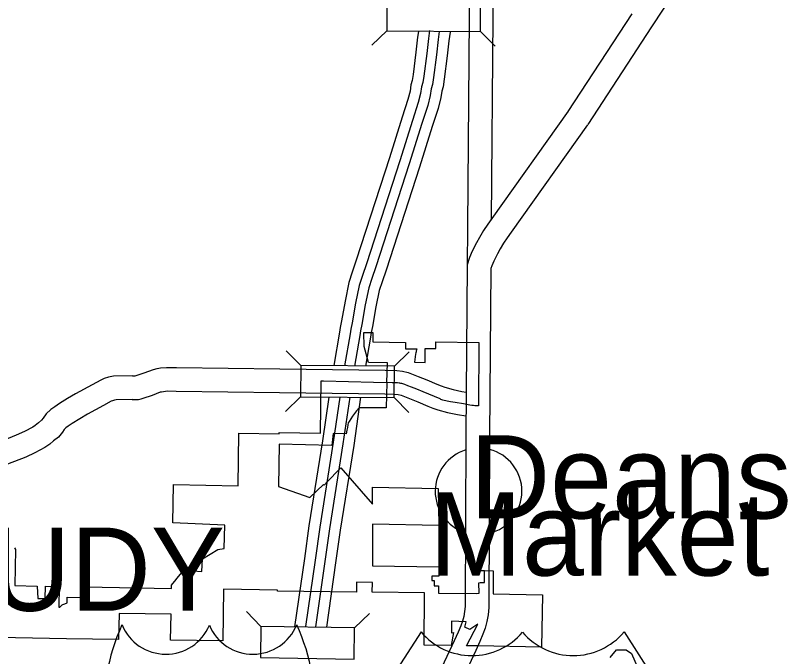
# Model space of a CAD drawing. Extents: x 535214 to 694517, y 381272 to 484355.
# Drawn here: x 552787 to 557684, y 468091 to 472159 of the extents above; entities that cross this region are included whole.
import ezdxf

# ---------------------------------------------------------------- set-up
doc = ezdxf.new("R2010")
doc.units = 0
for name, color, linetype in [('Level 11', 7, 'Continuous'), ('Level 15', 7, 'Continuous'), ('Level 19', 7, 'Continuous'), ('Level 20', 7, 'Continuous'), ('Level 22', 7, 'Continuous'), ('Level 23', 7, 'Continuous'), ('Level 24', 7, 'Continuous'), ('Level 6', 7, 'Continuous')]:
    doc.layers.add(name, color=color, linetype=linetype)

msp = doc.modelspace()

# ---------------------------------------------------------------- linework, layer by layer
at = {"layer": 'Level 11'}
for points in [[(555671.9, 472817.1), (555664.7, 472146.8), (555653.8, 470819.8), (555651.7, 470565.2)], [(555821.9, 472815.5), (555814.7, 472145.4), (555804.1, 470860.1)], [(553529.4, 469871.8), (553545.8, 469871.7), (553552, 469873.5), (553604.4, 469890.9), (553661.7, 469913.1), (553684.9, 469918.6), (553706.7, 469922), (553745.2, 469925.9), (553807.4, 469925.4), (554463.7, 469916.9), (555132.2, 469908.5), (555205, 469905.9), (555240.9, 469900.7), (555276.8, 469893.1), (555340.4, 469867.4), (555395.5, 469846.2), (555459.7, 469819), (555486.1, 469808.3), (555509.7, 469800.4), (555562.8, 469785.5), (555617.7, 469773.5), (555646.4, 469768.9)], [(553527.4, 469871.8), (553408.4, 469869.8), (553377.3, 469862.9), (553349.9, 469854.6), (553329.1, 469845.4), (553273.6, 469815.4), (553168.6, 469758.1), (553117.8, 469727.1), (553066.9, 469695.8), (553036.4, 469676.2), (553011.2, 469657.5), (552981.4, 469630.8), (552963.7, 469603.5), (552953.1, 469590.3), (552932.7, 469574), (552912.8, 469556.4), (552897.3, 469545.9), (552844.8, 469519.1), (552792.3, 469494.6), (552677.1, 469448.4)], [(553528, 469721.8), (553568, 469721.5), (553584.7, 469726.8), (553596.1, 469730.1), (553655.2, 469749.7), (553706.2, 469769.5), (553713.8, 469771.3), (553725.9, 469773.2), (553752.2, 469775.8), (553805.8, 469775.4), (554461.8, 469766.9), (555128.6, 469758.5), (555191.6, 469756.3), (555214.6, 469753), (555232.7, 469749.1), (555285.3, 469727.9), (555339.3, 469707.1), (555402.4, 469680.4), (555434.1, 469667.6), (555465.6, 469657), (555526.5, 469639.9), (555589.7, 469626.1), (555643, 469617.5)], [(553530, 469721.9), (553426.2, 469720.1), (553415.5, 469717.7), (553402.1, 469713.6), (553395.1, 469710.6), (553345.2, 469683.6), (553243.6, 469628.1), (553196.2, 469599.2), (553146.7, 469568.7), (553121.7, 469552.8), (553106.2, 469541.2), (553096.4, 469532.4), (553085.5, 469515.5), (553059.6, 469483.4), (553029.3, 469459.2), (553004.7, 469437.5), (552973.6, 469416.5), (552910.8, 469384.3), (552852, 469356.9), (552737.4, 469311)]]:
    msp.add_lwpolyline(points, dxfattribs=at)
at = {"layer": 'Level 15'}
for points in [[(557034.5, 472411.9), (556821.5, 472086.8), (556416.2, 471467)], [(556696, 472168.9), (556290.7, 471549.1)], [(556292.3, 471551.5), (555807.6, 470869.6), (555783.4, 470834.7), (555755, 470794.5), (555729.6, 470750.7), (555711, 470715.8), (555684.1, 470663.2), (555667.1, 470623.7), (555651.8, 470576.8), (555643.9, 469490.7), (555638.7, 468408.7), (555635.7, 468376.9), (555629.6, 468344.6), (555622, 468314.9), (555611.8, 468286.5), (555594.6, 468246.1), (555570.3, 468190.1), (555335.5, 467689.3)], [(556414.6, 471464.6), (555930.3, 470783.3), (555906.3, 470748.7), (555881.4, 470713.5), (555860.7, 470677.8), (555844, 470646.4), (555820, 470599.4), (555807.6, 470570.7), (555801.6, 470552.4), (555793.9, 469489.8), (555788.6, 468401.3), (555784.4, 468356), (555776.2, 468312.1), (555765.5, 468270.6), (555751.5, 468231.8), (555732.5, 468186.9), (555707, 468128.4), (555471.3, 467625.7)]]:
    msp.add_lwpolyline(points, dxfattribs=at)
at = {"layer": 'Level 19'}
for points in [[(555342.3, 472056.5), (555337.8, 472021.8), (555327, 471925.5), (555308.8, 471783.9), (555302.6, 471746.9), (555295.5, 471718.4), (555289.3, 471678.2), (555275.6, 471625), (555239.3, 471514.1), (555158.7, 471256.2), (554947.9, 470605.4), (554921.9, 470530.6), (554900.6, 470463.3), (554877, 470346.7), (554854, 470221.1), (554845.9, 470178.9), (554841.6, 470148.4), (554805.5, 469937.3)], [(555412.6, 472063.6), (555406, 472013.5), (555395.3, 471917.3), (555376.8, 471773.8), (555369.9, 471732.8), (555362.9, 471704.9), (555356.7, 471664.3), (555341.6, 471605.7), (555304.8, 471493.1), (555224.2, 471235.3), (555013.1, 470583.6), (554987.2, 470508.9), (554967.2, 470446), (554944.5, 470333.7), (554921.6, 470208.5), (554913.7, 470167.6), (554909.5, 470137.8), (554874.8, 469934.5)], [(555474.7, 472056.4), (555468.1, 472006), (555457.3, 471909.8), (555438.7, 471764.6), (555431.1, 471720.1), (555424.3, 471692.6), (555418.1, 471651.7), (555401.6, 471588.1), (555364.3, 471474.1), (555283.8, 471216.4), (555072.3, 470563.7), (555046.5, 470489.2), (555027.8, 470430.3), (555005.9, 470321.9), (554983, 470196.9), (554975.4, 470157.4), (554971.3, 470128.2), (554938.1, 469933.9)], [(555543.6, 472053.2), (555536.3, 471997.6), (555525.6, 471901.6), (555506.7, 471754.4), (555498.5, 471706), (555491.8, 471679.1), (555485.5, 471637.9), (555467.6, 471568.8), (555429.8, 471453.1), (555349.3, 471195.5), (555137.5, 470541.8), (555111.8, 470467.5), (555094.5, 470413.1), (555073.4, 470308.9), (555050.6, 470184.3), (555043.2, 470146.1), (555039.2, 470117.6), (555007.8, 469933.7)], [(554774.5, 469737.6), (554734.3, 469460.5), (554648.4, 468921.1), (554619.6, 468712.3), (554557.3, 468279.7)], [(554843.8, 469737), (554802.3, 469450.1), (554716.4, 468911), (554687.7, 468702.7), (554626.9, 468280.6)], [(554906.9, 469736.5), (554864.1, 469440.7), (554778.2, 468901.9), (554749.6, 468694), (554689.9, 468279.6)], [(554976.3, 469736), (554932.1, 469430.4), (554846.2, 468891.8), (554817.7, 468684.4), (554759.1, 468277.7)]]:
    msp.add_lwpolyline(points, dxfattribs=at)
at = {"layer": 'Level 20'}
for p, q in [((555141.8, 472062), (555047.7, 471969.4)), ((555735.7, 472057.3), (555828.3, 471963.2)), ((554596, 469937), (554503.4, 470031.1)), ((555190, 469932.3), (555284.1, 470024.9)), ((554594.5, 469739), (554500.4, 469646.4)), ((555188.4, 469734.3), (555281, 469640.2)), ((554344.2, 468282.4), (554252.4, 468377.3)), ((554938.1, 468272.4), (555033, 468364.2))]:
    msp.add_line(p, q, dxfattribs=at)
for points in [[(555141.8, 472062), (555735.7, 472057.3), (555737.3, 472255.3), (555143.3, 472260)], [(554594.5, 469739), (555188.4, 469734.3), (555190, 469932.3), (554596, 469937)], [(554938.1, 468272.4), (554344.2, 468282.4), (554340.8, 468084.4), (554934.7, 468074.5)]]:
    msp.add_lwpolyline(points, close=True, dxfattribs=at)
at = {"layer": 'Level 22'}
for p, q in [((555359.5, 468246.8), (555186.4, 467979.1)), ((556646.4, 468246.8), (556819.5, 467979.1))]:
    msp.add_line(p, q, dxfattribs=at)
for centre, start, end in [((555681.8, 468518), 220.075, 319.6701), ((556324.1, 468518), 220.3299, 319.925)]:
    msp.add_arc(centre, 421.2, start, end, dxfattribs=at)
at = {"layer": 'Level 23'}
for centre, radius, start, end in [((554579.6, 467776.6), 1230.1, 155.2204, 185.7928), ((553740.4, 468405.2), 299.7, 202.1459, 337.3414), ((554293.4, 468405.2), 299.7, 202.6586, 337.8541), ((553454.1, 467776.6), 1230.1, 354.2072, 24.7796)]:
    msp.add_arc(centre, radius, start, end, dxfattribs=at)
at = {"layer": 'Level 24'}
for start, end in [(107.1701, 251.8503), (284.3535, 75.3582)]:
    msp.add_arc((555724.1, 469139), 275, start, end, dxfattribs=at)
at = {"layer": 'Level 6'}
for points in [[(555026, 469956), (554997.5, 470058.7), (554995.8, 470147.1), (555053.8, 470146.1), (555053, 470087.5), (555261.5, 470084), (555261.2, 470043.5), (555332.4, 470042.3), (555330.6, 470035.8), (555328.9, 470029.6), (555327.4, 470023.7), (555326.4, 470018.6), (555325, 470009.1), (555322.5, 469993.6), (555317.3, 469958.8), (555385.6, 469957.6), (555386.3, 470045.6), (555452.2, 470044.5), (555452.6, 470088.3), (555726.3, 470083.7), (555723.5, 469681), (555700.4, 469682.5), (555691, 469683.4), (555682, 469684.6), (555669.6, 469686.5), (555659.1, 469688.3), (555627.8, 469693.7), (555576.6, 469702), (555546.7, 469706.9), (555535.4, 469709), (555525.9, 469710.8), (555517.5, 469712.7), (555506.4, 469715.7), (555497.9, 469718.4), (555485.3, 469722.8), (555479.5, 469725), (555445.5, 469739.8), (555373.5, 469771.1), (555333.1, 469787.5), (555298.8, 469800.9), (555275.7, 469809.5), (555255.5, 469816.7), (555243.7, 469820.6), (555237, 469822.3), (555230.3, 469823.9), (555225.2, 469825), (555219.9, 469825.9), (555210.3, 469826.9), (555201.3, 469827.4), (555177, 469828.3), (555141.3, 469829.5)], [(555141.3, 469829.5), (555145.9, 469954.7), (555026, 469956)], [(552780.9, 468781.4), (552788.4, 468770.8), (552783.5, 468540.5), (552924.5, 468537.8), (552929.6, 468459.9), (552975.7, 468458.9), (552976.8, 468536.8), (553063.4, 468535.1), (553062.7, 468403.6), (553063.5, 468403.7), (553065.1, 468403.8), (553066, 468404), (553067.4, 468404.3), (553068.5, 468404.6), (553069.8, 468405.4), (553070.8, 468406.3), (553076.9, 468413.4), (553079.2, 468415.4), (553080.9, 468416.7), (553082.8, 468417.9), (553084.3, 468418.8), (553088.2, 468420.8), (553094, 468423.3), (553110.3, 468429.6), (553115.4, 468432.5), (553116, 468466.5), (553226.2, 468464.6), (553227.3, 468532.2), (553777, 468523), (553777.4, 468543), (553785.8, 468554.8), (553797.3, 468570), (553812.6, 468589.1), (553842.9, 468624.5), (553855.4, 468639.8), (553969.2, 468630.2), (553972.5, 468711.5), (554071.2, 468770.4), (554111.5, 468776.1), (554112.7, 468849.4), (554114, 468923.6), (553784.2, 468938.2), (553788.4, 469182.3), (554200, 469174.2), (554204.4, 469508.6), (554460.3, 469504.3), (554460.4, 469513.4), (554722, 469508), (554726.9, 469840.4), (554740.4, 469840.2), (555056.8, 469832.4), (555141.3, 469829.5)], [(555141.3, 469829.5), (555138.1, 469669.3), (554966.2, 469669.6), (554950.1, 469649.6), (554937.4, 469632.7), (554924.8, 469615.1), (554914.2, 469598.5), (554902.6, 469582.7), (554898, 469572.8), (554894.9, 469560.2), (554893.1, 469544), (554888.9, 469526.4), (554884.2, 469504.7), (554801.8, 469506.4), (554792.5, 469429.9), (554459.2, 469438.5), (554454.6, 469169.8), (554654.3, 469099), (554740.6, 469182.3), (554745.7, 469177.9), (554758.3, 469191.4), (554758.6, 469192.8), (554850, 469288.6), (555051.2, 469057.1), (555051.4, 469164.6), (555468.4, 469157.7), (555471.1, 468923.1), (555051, 468930), (555050.6, 468666.6), (555472.4, 468660.4), (555471.7, 468599.8), (555426.9, 468600.3), (555426.9, 468573.1), (555441.8, 468572.9), (555441.7, 468540.3), (555471, 468539.9), (555470.5, 468493.8), (555712.5, 468490.8), (555727.3, 468493.9), (555726.6, 468558.1), (555734.5, 468561), (555761.5, 468560), (555761.5, 468634.2), (555712.7, 468635.1), (555712.7, 468637.6), (555816, 468634), (555816.8, 468488.5)], [(555816.8, 468488.5), (556129.3, 468481.4), (556122.9, 468149.3), (555719.9, 468157.8), (555648.5, 468158.7), (555720.2, 468296.2), (555669, 468262.1), (555637.2, 468277.6), (555644.8, 468310.4), (555553, 468315.1), (555553, 468241.6), (555565.5, 468242.5), (555550.9, 468159.8), (555379.8, 468161.9), (555380.3, 468494.9), (555050.3, 468499), (555050.4, 468560.8), (554949.4, 468562.1), (554949.3, 468500.2), (554448.1, 468506.4), (554448.1, 468511.7), (554107, 468517.4), (554101.3, 468189.5), (553771.4, 468194.4), (553774.2, 468358.7), (553444.2, 468363.9), (553441.4, 468199.2), (553111.4, 468204.1), (552246.4, 468220.7)], [(556559.6, 468084.4), (556599.6, 468133.2), (556659.9, 468132.3), (556694, 468109.1), (556757.7, 467964.2)]]:
    msp.add_lwpolyline(points, dxfattribs=at)

# ---------------------------------------------------------------- texts
at = {"layer": 'Level 24'}
for s, p in [('Deans', (555668.2, 468966.7)), ('Market', (555411.6, 468604.6))]:
    msp.add_text(s, height=528, dxfattribs=at).set_placement(p)
at = {"layer": 'Level 6'}
msp.add_text('RUDY', height=528, dxfattribs=at).set_placement((552116.1, 468380.9))

doc.saveas('drawing.dxf')
